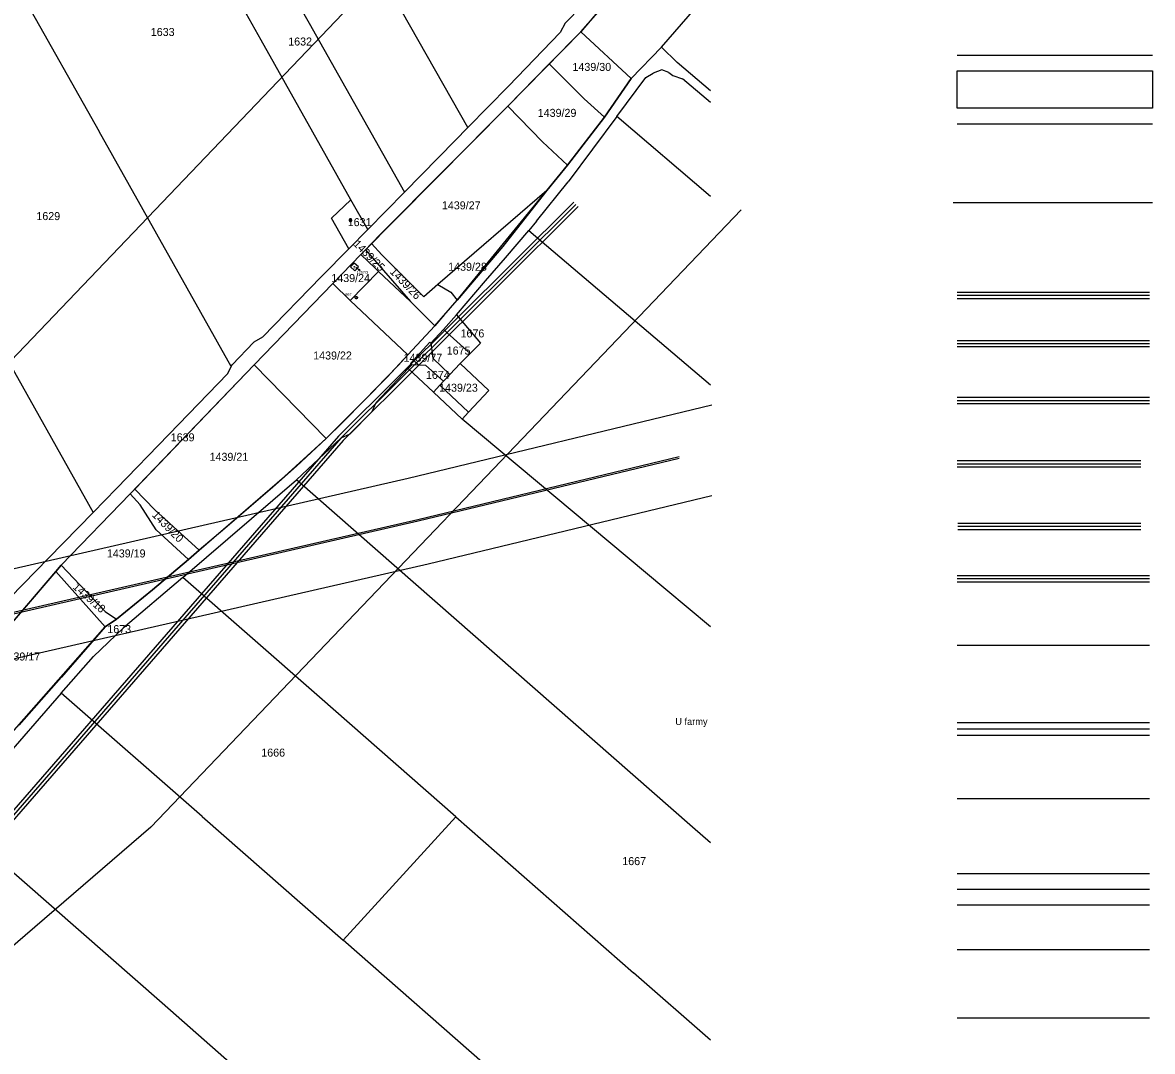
# Model space of a CAD drawing. Extents: x -510185 to -506993, y -1126306 to -1123642.
# Drawn here: x -508329 to -507609, y -1125159 to -1124503 of the extents above; entities that cross this region are included whole.
import ezdxf

# ---------------------------------------------------------------- set-up
doc = ezdxf.new("R2010")
doc.units = 0
for name, color, linetype in [('parcelni hranice', 7, 'Continuous'), ('u_dalnice', 7, 'Continuous'), ('u_legenda', 7, 'Continuous'), ('u_VaK', 7, 'Continuous'), ('u_Vak_přivad', 7, 'Continuous'), ('u_ČEPS nadzemní VVN', 7, 'Continuous'), ('ČEPS', 7, 'Continuous'), ('ˇ2', 7, 'Continuous'), ('ˇ3', 7, 'Continuous'), ('ˇ4', 7, 'Continuous'), ('ˇ5', 7, 'Continuous'), ('ˇ7', 7, 'Continuous'), ('ˇ8', 7, 'Continuous')]:
    doc.layers.add(name, color=color, linetype=linetype)

msp = doc.modelspace()

# ---------------------------------------------------------------- linework, layer by layer
at = {"layer": 'parcelni hranice'}
for p, q in [((-508207.35, -1124395.84), (-508146.57, -1124503.56)), ((-508177.16, -1124514.37), (-508234.39, -1124412.68)), ((-508045.5, -1124570.11), (-508133.48, -1124414.2)), ((-508364.73, -1124422.86), (-508280.46, -1124572.58)), ((-507973.48, -1124508.95), (-507954.7, -1124487.54)), ((-507972.89, -1124492.57), (-507983.38, -1124503.54)), ((-507922.09, -1124518.87), (-507900.83, -1124494.41)), ((-508146.57, -1124503.56), (-508085.79, -1124611.29)), ((-507983.38, -1124503.54), (-507986.64, -1124509.41)), ((-508019.63, -1124543.63), (-507986.64, -1124509.41)), ((-507993.57, -1124529.42), (-507973.48, -1124508.95)), ((-507973.48, -1124508.95), (-507941.45, -1124538.71)), ((-508119.93, -1124616.06), (-508177.16, -1124514.37)), ((-507922.09, -1124518.87), (-507941.45, -1124538.71)), ((-507912.09, -1124528.47), (-507922.09, -1124518.87)), ((-508020.02, -1124556.37), (-507993.57, -1124529.42)), ((-507971.28, -1124551.7), (-507993.57, -1124529.42)), ((-507921.91, -1124533.2), (-507927.41, -1124535.27)), ((-507917.35, -1124534.84), (-507921.91, -1124533.2)), ((-507890.86, -1124546.63), (-507912.09, -1124528.47)), ((-507941.45, -1124538.71), (-507958.29, -1124563.4)), ((-507950.52, -1124563.09), (-507932.01, -1124538.14)), ((-507932.01, -1124538.14), (-507927.41, -1124535.27)), ((-507917.35, -1124534.84), (-507914.73, -1124536.92)), ((-507914.73, -1124536.92), (-507908.56, -1124538.89)), ((-507890.86, -1124554.06), (-507908.56, -1124538.89)), ((-508045.5, -1124570.11), (-508019.63, -1124543.63)), ((-507958.29, -1124563.4), (-507971.28, -1124551.7)), ((-508101.04, -1124638), (-508020.02, -1124556.37)), ((-507997.97, -1124579.14), (-508020.02, -1124556.37)), ((-507958.29, -1124563.4), (-507981.89, -1124593.96)), ((-507950.52, -1124563.09), (-507981.61, -1124604.68)), ((-507890.86, -1124613.92), (-507950.52, -1124563.09)), ((-508196.2, -1124722.28), (-508280.46, -1124572.58)), ((-508045.5, -1124570.11), (-508053.6, -1124578.4)), ((-508085.79, -1124611.29), (-508053.6, -1124578.4)), ((-507981.89, -1124593.96), (-507997.97, -1124579.14)), ((-507981.89, -1124593.96), (-507995.01, -1124610.08)), ((-508001.64, -1124629.78), (-507981.61, -1124604.68)), ((-508109.17, -1124635.12), (-508085.79, -1124611.29)), ((-507995.01, -1124610.08), (-508064.52, -1124670.17)), ((-507995.01, -1124610.08), (-508023.24, -1124645.97)), ((-508132.38, -1124627.89), (-508119.93, -1124616.06)), ((-508109.17, -1124635.12), (-508119.93, -1124616.06)), ((-508121.31, -1124647.46), (-508132.38, -1124627.89)), ((-508001.64, -1124629.78), (-508006.55, -1124635.59)), ((-508109.17, -1124635.12), (-508121.31, -1124647.46)), ((-508106.88, -1124643.87), (-508101.04, -1124638)), ((-508021.42, -1124653.19), (-508006.55, -1124635.59)), ((-508006.55, -1124635.59), (-507890.86, -1124734.14)), ((-508138.77, -1124664.95), (-508121.31, -1124647.46)), ((-508113.67, -1124650.93), (-508110.78, -1124647.92)), ((-508110.78, -1124647.92), (-508106.88, -1124643.87)), ((-508110.78, -1124647.92), (-508082.07, -1124680.9)), ((-508100.31, -1124651.14), (-508106.88, -1124643.87)), ((-508023.24, -1124645.97), (-508052.25, -1124680.1)), ((-508131.47, -1124669.39), (-508113.67, -1124650.93)), ((-508113.67, -1124650.93), (-508104.3, -1124659.9)), ((-508073.5, -1124677.94), (-508100.31, -1124651.14)), ((-508034.17, -1124667.86), (-508021.42, -1124653.19)), ((-508120.4, -1124680.32), (-508102.36, -1124661.76)), ((-508117.92, -1124656.45), (-508120.29, -1124658.73)), ((-508120.29, -1124658.73), (-508117.55, -1124661.4)), ((-508115.21, -1124658.89), (-508117.92, -1124656.45)), ((-508117.55, -1124661.4), (-508115.21, -1124658.89)), ((-508104.3, -1124659.9), (-508102.36, -1124661.76)), ((-508102.36, -1124661.76), (-508082.07, -1124680.9)), ((-508181.53, -1124721.36), (-508131.47, -1124669.39)), ((-508138.77, -1124664.95), (-508176.32, -1124703.76)), ((-508131.47, -1124669.39), (-508120.4, -1124680.32)), ((-508064.52, -1124670.17), (-508073.5, -1124677.94)), ((-508064.52, -1124670.17), (-508056.24, -1124674.95)), ((-508052.77, -1124689.35), (-508034.17, -1124667.86)), ((-508056.24, -1124674.95), (-508052.25, -1124680.1)), ((-508358.73, -1124682.64), (-508284.33, -1124815.5)), ((-508082.07, -1124680.9), (-508066.59, -1124696.52)), ((-508052.25, -1124680.1), (-508060.27, -1124689.33)), ((-508060.27, -1124689.33), (-508066.59, -1124696.52)), ((-508052.77, -1124689.35), (-508060.96, -1124698.81)), ((-508052.77, -1124689.35), (-508037.39, -1124707.45)), ((-508066.59, -1124696.52), (-508083.69, -1124714.98)), ((-508068.94, -1124707.55), (-508060.96, -1124698.81)), ((-508044.01, -1124714.1), (-508060.96, -1124698.81)), ((-508176.32, -1124703.76), (-508181.8, -1124706.82)), ((-508195.67, -1124721.23), (-508181.8, -1124706.82)), ((-508080.1, -1124718.37), (-508069.7, -1124706.86)), ((-508069.7, -1124706.86), (-508068.94, -1124707.55)), ((-508068.94, -1124707.55), (-508067.87, -1124716.97)), ((-508044.01, -1124714.1), (-508037.39, -1124707.45)), ((-508083.69, -1124714.98), (-508096.8, -1124729.15)), ((-508082.04, -1124720.51), (-508080.1, -1124718.37)), ((-508081.16, -1124721.26), (-508082.04, -1124720.51)), ((-508067.87, -1124716.97), (-508056.93, -1124727.53)), ((-508050.38, -1124720.51), (-508056.93, -1124727.53)), ((-508044.01, -1124714.1), (-508050.38, -1124720.51)), ((-508032.1, -1124737.57), (-508050.38, -1124720.51)), ((-508257.59, -1124800.55), (-508181.53, -1124721.36)), ((-508198.51, -1124726.82), (-508235.98, -1124765.7)), ((-508198.51, -1124726.82), (-508196.2, -1124722.28)), ((-508196.2, -1124722.28), (-508195.67, -1124721.23)), ((-508181.53, -1124721.36), (-508135.77, -1124768.3)), ((-508103.89, -1124745.22), (-508083.55, -1124723.63)), ((-508083.55, -1124723.63), (-508081.16, -1124721.26)), ((-508083.55, -1124723.63), (-508067.43, -1124738.79)), ((-508076.79, -1124721.49), (-508081.16, -1124721.26)), ((-508072.32, -1124721.73), (-508076.79, -1124721.49)), ((-508060.89, -1124731.77), (-508072.32, -1124721.73)), ((-508060.89, -1124731.77), (-508056.93, -1124727.53)), ((-508096.8, -1124729.15), (-508125.36, -1124758.11)), ((-508063.24, -1124734.29), (-508067.43, -1124738.79)), ((-508060.89, -1124731.77), (-508063.24, -1124734.29)), ((-508067.43, -1124738.79), (-508049.16, -1124755.85)), ((-508045.06, -1124751.45), (-508032.1, -1124737.57)), ((-508106.5, -1124751.08), (-508103.89, -1124745.22)), ((-508106.5, -1124751.08), (-508120.58, -1124765.41)), ((-508049.16, -1124755.85), (-508045.06, -1124751.45)), ((-507919.35, -1124864.53), (-508049.16, -1124755.85)), ((-508125.36, -1124758.11), (-508135.77, -1124768.3)), ((-508235.98, -1124765.7), (-508269.33, -1124800.1)), ((-508154.7, -1124794.57), (-508126.38, -1124768.09)), ((-508135.77, -1124768.3), (-508154.64, -1124785.9)), ((-508120.58, -1124765.41), (-508126.38, -1124768.09)), ((-508154.64, -1124785.9), (-508169.79, -1124799.26)), ((-508269.33, -1124800.1), (-508284.33, -1124815.5)), ((-508227.06, -1124856.9), (-508154.7, -1124794.57)), ((-508169.79, -1124799.26), (-508200.3, -1124825.7)), ((-508028.5, -1124905.27), (-508154.7, -1124794.57)), ((-508304.56, -1124849.12), (-508260.65, -1124803.65)), ((-508260.65, -1124803.65), (-508257.59, -1124800.55)), ((-508254.23, -1124810.5), (-508260.65, -1124803.65)), ((-508245.02, -1124813.69), (-508257.59, -1124800.55)), ((-508244.15, -1124826.46), (-508254.23, -1124810.5)), ((-508216.68, -1124839.43), (-508245.02, -1124813.69)), ((-508284.33, -1124815.5), (-508312.65, -1124844.58)), ((-508223.53, -1124845.36), (-508244.15, -1124826.46)), ((-508200.3, -1124825.7), (-508216.68, -1124839.43)), ((-508216.68, -1124839.43), (-508223.53, -1124845.36)), ((-508349.32, -1124881.91), (-508312.65, -1124844.58)), ((-508307.98, -1124853.09), (-508304.56, -1124849.12)), ((-508304.56, -1124849.12), (-508276.59, -1124878.56)), ((-508223.53, -1124845.36), (-508246.42, -1124864.83)), ((-508351.15, -1124903.3), (-508307.98, -1124853.09)), ((-508276.53, -1124888.42), (-508307.98, -1124853.09)), ((-508227.06, -1124856.9), (-508265.11, -1124889.2)), ((-508140.1, -1124933.18), (-508227.06, -1124856.9)), ((-508246.42, -1124864.83), (-508269.37, -1124883.48)), ((-507890.86, -1124888.38), (-507919.35, -1124864.53)), ((-508276.59, -1124878.56), (-508269.37, -1124883.48)), ((-508269.37, -1124883.48), (-508276.53, -1124888.42)), ((-508276.53, -1124888.42), (-508304.45, -1124920.5)), ((-508284, -1124907.2), (-508265.11, -1124889.2)), ((-508304.54, -1124930.54), (-508284, -1124907.2)), ((-507902.3, -1125015.97), (-508028.5, -1124905.27)), ((-508304.45, -1124920.5), (-508331.34, -1124950.99)), ((-508304.54, -1124930.54), (-508347.3, -1124979.68)), ((-508214.76, -1125009.3), (-508304.54, -1124930.54)), ((-508053.15, -1125009.45), (-508140.1, -1124933.18)), ((-508368.21, -1125015.89), (-508240.31, -1125128.08)), ((-508214.76, -1125009.3), (-508124.97, -1125088.05)), ((-508124.97, -1125088.05), (-508053.15, -1125009.45)), ((-508053.15, -1125009.45), (-507939.83, -1125108.85)), ((-507890.86, -1125026.01), (-507902.3, -1125015.97)), ((-508011.65, -1125187.45), (-508124.97, -1125088.05)), ((-507890.86, -1125151.8), (-507939.83, -1125108.85)), ((-508240.31, -1125128.08), (-508112.4, -1125240.27))]:
    msp.add_line(p, q, dxfattribs=at)
at = {"layer": 'u_dalnice'}
for points in [[(-507931.94, -1124295.07), (-508433.56, -1124819.97), (-508560.91, -1124929.62)], [(-507950.92, -1124482.29), (-507973.48, -1124508.95), (-508020.02, -1124556.37), (-508113.67, -1124650.93), (-508131.47, -1124669.39), (-508181.53, -1124721.36), (-508260.65, -1124803.65), (-508304.56, -1124849.12), (-508307.98, -1124853.09), (-508351.15, -1124903.3)], [(-508350.21, -1124971.95), (-508276.53, -1124888.42), (-508269.37, -1124883.48), (-508246.42, -1124864.83), (-508223.53, -1124845.36), (-508216.68, -1124839.43), (-508162.22, -1124792.58), (-508135.77, -1124768.3), (-508111.08, -1124743.63), (-508089.87, -1124721.83), (-508083.69, -1124714.98), (-508066.59, -1124696.52), (-508052.25, -1124680.1), (-507995.01, -1124610.08), (-507981.89, -1124593.96), (-507958.29, -1124563.4), (-507941.45, -1124538.71), (-507922.09, -1124518.87), (-507900.83, -1124494.41)], [(-507871.36, -1124622.47), (-508247.43, -1125016), (-508412.62, -1125158.24)]]:
    msp.add_lwpolyline(points, dxfattribs=at)
at = {"layer": 'u_legenda'}
for p, q in [((-507733.66, -1124523.91), (-507609.17, -1124523.91)), ((-507733.66, -1124567.69), (-507609.17, -1124567.69)), ((-507736.13, -1124617.88), (-507609.17, -1124617.88)), ((-507733.66, -1124674.98), (-507611.06, -1124674.98)), ((-507733.66, -1124676.98), (-507611.06, -1124676.98)), ((-507733.66, -1124678.98), (-507611.06, -1124678.98)), ((-507733.66, -1124705.71), (-507611.06, -1124705.71)), ((-507733.66, -1124707.71), (-507611.06, -1124707.71)), ((-507733.66, -1124709.71), (-507611.06, -1124709.71)), ((-507733.66, -1124741.95), (-507611.06, -1124741.95)), ((-507733.66, -1124743.95), (-507611.06, -1124743.95)), ((-507733.66, -1124745.95), (-507611.06, -1124745.95)), ((-507733.66, -1124782.34), (-507616.47, -1124782.34)), ((-507733.66, -1124784.34), (-507616.47, -1124784.34)), ((-507733.66, -1124786.34), (-507616.47, -1124786.34)), ((-507733.25, -1124822.19), (-507616.47, -1124822.19)), ((-507733.25, -1124824.19), (-507616.47, -1124824.19)), ((-507733.25, -1124826.19), (-507616.47, -1124826.19)), ((-507733.66, -1124855.56), (-507611.06, -1124855.56)), ((-507733.66, -1124857.56), (-507611.06, -1124857.56)), ((-507733.66, -1124859.56), (-507611.06, -1124859.56)), ((-507733.66, -1124899.99), (-507611.06, -1124899.99)), ((-507733.66, -1124949.41), (-507611.06, -1124949.41)), ((-507733.66, -1124953.41), (-507611.06, -1124953.41)), ((-507733.66, -1124957.41), (-507611.06, -1124957.41)), ((-507733.66, -1124997.68), (-507611.06, -1124997.68)), ((-507733.66, -1125045.6), (-507611.06, -1125045.6)), ((-507733.66, -1125055.6), (-507611.06, -1125055.6)), ((-507733.66, -1125065.6), (-507611.06, -1125065.6)), ((-507733.66, -1125093.95), (-507611.06, -1125093.95)), ((-507733.66, -1125137.51), (-507611.06, -1125137.51))]:
    msp.add_line(p, q, dxfattribs=at)
msp.add_lwpolyline([(-507733.66, -1124533.91), (-507609.17, -1124533.91), (-507609.17, -1124557.69), (-507733.66, -1124557.69)], close=True, dxfattribs=at)
msp.add_lwpolyline([(-507733.66, -1124533.91), (-507609.17, -1124533.91), (-507609.17, -1124557.69), (-507733.66, -1124557.69)], close=True, dxfattribs=at)
at = {"layer": 'u_VaK'}
for points in [[(-507978.01, -1124617.61), (-508127.84, -1124766.72), (-508433.56, -1125118.56), (-508471.06, -1125179.03), (-508517.15, -1125229.42), (-508712.18, -1125376.76), (-508775.25, -1125375.7), (-508900.26, -1125411.57), (-508965.16, -1125311.22), (-509031.97, -1125364.95), (-509327.71, -1125507.59)], [(-507975.18, -1124620.45), (-508124.92, -1124769.46), (-508430.33, -1125120.94), (-508467.86, -1125181.45), (-508512.91, -1125230.71)]]:
    msp.add_lwpolyline(points, dxfattribs=at)
at = {"layer": 'u_Vak_přivad'}
msp.add_lwpolyline([(-507976.59, -1124619.03), (-508126.38, -1124768.09), (-508431.95, -1125119.75), (-508469.46, -1125180.24), (-508515.79, -1125230.9), (-508711.52, -1125378.77), (-508774.98, -1125377.71), (-508901.13, -1125413.9), (-508965.64, -1125314.16), (-509030.89, -1125366.66), (-509326.84, -1125509.39)], dxfattribs=at)
at = {"layer": 'u_ČEPS nadzemní VVN'}
for points in [[(-510185.05, -1125336.69), (-510011.44, -1125269.94), (-509690.54, -1125194.07), (-509367.08, -1125118.37), (-509051.23, -1125043.52), (-508723.83, -1124966.6), (-508395.54, -1124892.88), (-508077.37, -1124819.87), (-507910.72, -1124779.68)], [(-510185.05, -1125337.76), (-510011.14, -1125270.9), (-509690.31, -1125195.05), (-509366.85, -1125119.34), (-509051.01, -1125044.5), (-508723.61, -1124967.57), (-508395.32, -1124893.85), (-508077.14, -1124820.84), (-507910.72, -1124780.71)]]:
    msp.add_lwpolyline(points, dxfattribs=at)
at = {"layer": 'ČEPS'}
for points in [[(-510185.05, -1125307.76), (-510019.43, -1125244.08), (-509696.72, -1125167.79), (-509373.27, -1125092.09), (-509057.44, -1125017.25), (-508729.88, -1124940.28), (-508401.51, -1124866.55), (-508083.55, -1124793.59), (-507890, -1124746.91)], [(-510185.05, -1125367.76), (-510002.86, -1125297.71), (-509683.9, -1125222.3), (-509360.43, -1125146.6), (-509044.57, -1125071.75), (-508717.34, -1124994.86), (-508389.12, -1124921.16), (-508070.72, -1124848.1), (-507890, -1124804.52)]]:
    msp.add_lwpolyline(points, dxfattribs=at)
at = {"layer": 'ˇ3'}
msp.add_lwpolyline([(-508121.21, -1124629.1), (-508119.21, -1124629.1)], dxfattribs=at)
msp.add_lwpolyline([(-508120.71, -1124628.6), (-508120.61, -1124628.31), (-508120.36, -1124628.12), (-508120.05, -1124628.12), (-508119.8, -1124628.31), (-508119.71, -1124628.6), (-508119.71, -1124629.6), (-508119.8, -1124629.89), (-508120.05, -1124630.08), (-508120.36, -1124630.08), (-508120.61, -1124629.89), (-508120.71, -1124629.6)], close=True, dxfattribs=at)
at = {"layer": 'ˇ4'}
for p, q in [((-508120.4, -1124680.32), (-508083.69, -1124714.98)), ((-508080.1, -1124718.37), (-508076.79, -1124721.49)), ((-508063.24, -1124734.29), (-508045.06, -1124751.45))]:
    msp.add_line(p, q, dxfattribs=at)
at = {"layer": 'ˇ5'}
msp.add_lwpolyline([(-508117.69, -1124658.66), (-508117.61, -1124658.81), (-508117.69, -1124658.96), (-508117.87, -1124658.96), (-508117.96, -1124658.81), (-508117.87, -1124658.66)], close=True, dxfattribs=at)
at = {"layer": 'ˇ7'}
msp.add_line((-508116.89, -1124659.25), (-508116.68, -1124659.4), dxfattribs=at)
for points in [[(-508114.2, -1124661.09), (-508116.68, -1124659.4)], [(-508114.75, -1124660.11), (-508114.2, -1124661.09), (-508115.31, -1124660.94)]]:
    msp.add_lwpolyline(points, dxfattribs=at)
at = {"layer": 'ˇ8'}
msp.add_lwpolyline([(-508116.34, -1124677.73), (-508116, -1124677.92), (-508115.81, -1124678.26), (-508115.81, -1124678.64), (-508116, -1124678.98), (-508116.34, -1124679.17), (-508116.72, -1124679.17), (-508117.06, -1124678.98), (-508117.25, -1124678.64), (-508117.25, -1124678.26), (-508117.06, -1124677.92), (-508116.72, -1124677.73)], close=True, dxfattribs=at)
msp.add_lwpolyline([(-508116.58, -1124678.45), (-508116.48, -1124678.45)], dxfattribs=at)

# ---------------------------------------------------------------- texts
at = {"layer": 'ˇ2'}
for s, height, p in [('1633', 5.1, (-508247.52, -1124511.65)), ('1632', 5.1, (-508159.94, -1124517.74)), ('1439/30', 5.1, (-507978.78, -1124533.93)), ('1439/29', 5.1, (-508000.91, -1124563.22)), ('1439/27', 5.1, (-508061.99, -1124622.2)), ('1629', 5.1, (-508320.44, -1124629.04)), ('1631', 5.1, (-508122.02, -1124632.9)), ('1439/28', 5.1, (-508057.99, -1124661.33)), ('1439/24', 5.1, (-508132.47, -1124668.54)), ('1257/3', 0.3, (-508118.43, -1124659.96)), ('1676', 5.1, (-508050.11, -1124703.83)), ('1439/22', 5.1, (-508144.02, -1124717.91)), ('1675', 5.1, (-508058.93, -1124714.77)), ('1439/77', 5.1, (-508086.41, -1124719.36)), ('1674', 5.1, (-508072.17, -1124730.28)), ('1439/23', 5.1, (-508063.76, -1124738.44)), ('1639', 5.1, (-508234.81, -1124770.08)), ('1439/21', 5.1, (-508210.06, -1124782.5)), ('1439/19', 5.1, (-508275.51, -1124844.09)), ('1673', 5.1, (-508275.22, -1124892.34)), ('1439/17', 5.1, (-508342.63, -1124909.79)), ('1666', 5.1, (-508177.1, -1124971.08)), ('1667', 5.1, (-507947.04, -1125040.24))]:
    msp.add_text(s, height=height, dxfattribs=at).set_placement(p)
for s, rotation, p in [('1439/25', 315.01219, (-508118.79, -1124644.75)), ('1439/26', 313.80898, (-508095.5, -1124662.34)), ('1439/20', 314.61113, (-508247.08, -1124817.46)), ('1439/18', 318.62183, (-508297.68, -1124863.51))]:
    msp.add_text(s, height=5.1, rotation=rotation, dxfattribs=at).set_placement(p)
at = {"layer": 'ˇ7'}
for s, height, p in [('1257/3', 1.7, (-508116.28, -1124663.21)), ('U farmy', 4.4, (-507913.26, -1124950.92))]:
    msp.add_text(s, height=height, dxfattribs=at).set_placement(p)
at = {"layer": 'ˇ8'}
msp.add_text('667', height=1.7, dxfattribs=at).set_placement((-508123.53, -1124677.25))

doc.saveas('drawing.dxf')
